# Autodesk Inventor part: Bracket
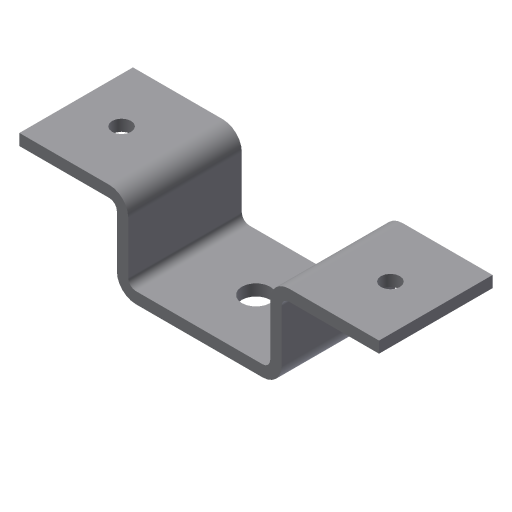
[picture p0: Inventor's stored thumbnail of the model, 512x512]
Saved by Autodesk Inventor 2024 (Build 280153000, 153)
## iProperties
Shininess: 64.0
Length Units: 11269
Angle Units: 11279
Time Units: 11290
Mass Units: 11283
Length Display Precision: 3
Angle Display Precision: 2
Compacted: True
Part Number: Bracket
Document SubType Name: Modeling
Created: 2003-01
Designer: Owner
Density: 1 g/cm^3
Material: Generic
Appearance: Default
Density: 0.0
Volumn: 0.0
Area: 0.0
PropertySet Name: Model Information
Control State: 0
Master: False
Checked Out: False
Author: Owner
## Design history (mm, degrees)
sketch "Sketch2"
  geometry: L1 (487.39, 112.858)-(199.89, 112.858); L2 (199.89, 112.858)-(199.89, -95.142); L3 (199.89, -95.142)-(-175.11, -95.142); L4 (-175.11, -95.142)-(-175.11, 112.858); L5 (-175.11, 112.858)-(-462.61, 112.858); L6 (-462.61, 82.858)-(-205.11, 82.858); L7 (-205.11, 82.858)-(-205.11, -125.142); L8 (-205.11, -125.142)-(229.89, -125.142); L9 (229.89, -125.142)-(229.89, 82.858); L10 (229.89, 82.858)-(487.39, 82.858); L11 (487.39, 112.858)-(487.39, 82.858); L12 (-462.61, 112.858)-(-462.61, 82.858)
  constraints: 24 end point, 5 parallel, 3 perpendicular, 2 collinear, 2 equal length, 1 horizontal, 4 other
  dimensions: "d0" = 375 distance between parallel lines of L4 L2; "d1" = 950 distance of L5.end L1.start; "d2" = 30 distance between parallel lines of L1 L10; "d3" = 238 distance between parallel lines of L5 L8
extrude "Extrusion1" new body sketch "Sketch2" stored distance "d4" = 300; taper "d5" = 0 deg
fillet "Fillet1" dims "d6" = 20
fillet "Fillet2" dims "d7" = 50
sketch "Sketch3"
  geometry: L1 (237.5, 300)-(0, 300) reference; L2 (0, 300)-(0, 0) reference; 1 further point
  dimensions: "d8" = 120 distance from line of L2 point (120, 150); "d9" = 150 distance from line of L1 point (120, 150)
hole "Hole1" sketch "Sketch3" diameter "d10" = 50; stored, may be unused: countersink angle "d14" = 82 deg, drill point angle "d16" = 118 deg; dims "d11" = 6, "d12" = 4, "d13" = 2, "d15" = 8
pattern_linear "Rectangular Pattern1" dims "d19" = 710
sketch "Sketch4"
  geometry: L1 (0, -300)-(335, -300) reference; 1 further point
  dimensions: "d20" = 150 distance from line of L1 point (167.5, -150)
hole "Hole2" sketch "Sketch4" at (167.5, -150) diameter "d21" = 75; stored, may be unused: countersink angle "d25" = 82 deg, drill point angle "d27" = 118 deg; dims "d22" = 6, "d23" = 4, "d24" = 2, "d26" = 8
body "Solid1"
node "Sketch1"
